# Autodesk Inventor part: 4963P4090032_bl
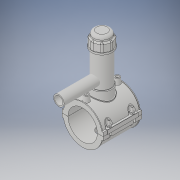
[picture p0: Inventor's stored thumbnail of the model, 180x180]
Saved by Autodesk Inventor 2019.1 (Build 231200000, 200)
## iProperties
Created: 2017-07
Part Number: 4963P4090032_bl
Material: Generic
Document SubType Name: Modeling
Designer: KIM
Density: 1 g/cm^3
Appearance: Default
Author: KIM
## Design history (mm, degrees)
derived "4963P4.ipt"
feature "Solid1::4963P4.ipt" dims "ScaleForDerivedMember" = 10
feature "Solid2::4963P4.ipt" dims "ScaleForDerivedMember" = 10
feature "Solid3::4963P4.ipt" dims "ScaleForDerivedMember" = 10
tag "TaggingFeature1"
body "Solid1"
body "Solid2"
body "Solid3"
other parameters: "d2" = 126 [user parameter], "d3" = 22.5 [user parameter], "d4" = 118 [user parameter], "d5" = 0 [user parameter], "d6" = 0.1 [user parameter], "d8" = 0 [user parameter], "d19" = 6 [user parameter], "d20" = 6 [user parameter], "d21" = 70.8 [user parameter], "d23" = 0 [user parameter], "d24" = 35.4 [user parameter], "d26" = 0 [user parameter], "d27" = 3 [user parameter], "d28" = 3 [user parameter], "d29" = 3 [user parameter], "d31" = 6 [user parameter], "d32" = 0 [user parameter], "d33" = 0 [user parameter], "d34" = 0.6 [user parameter], "d40" = 60.84 [user parameter], "d41" = 63 [user parameter], "d43" = 0 [user parameter], "d45" = 0 [user parameter], "d47" = 129.3 [user parameter], "d70" = 15 [user parameter], "d72" = 0 [user parameter], "d73" = 6 [user parameter], "d75" = 5 [user parameter], "d76" = 0 [user parameter], "d77" = 4.5 [user parameter], "d78" = 75 [user parameter], "d79" = 15 [user parameter], "d80" = 47.2 [user parameter], "d82" = 5 deg [user parameter], "d84" = 4 [user parameter], "d85" = 14 [user parameter], "d86" = 0 [user parameter], "d87" = 3 [user parameter], "d88" = 0 [user parameter], "d89" = 1 [user parameter], "d90" = 1 [user parameter], "d91" = 94.4 [user parameter], "d92" = 0 [user parameter], "d93" = 0.5 [user parameter], "d94" = 47.36842 [user parameter], "d96" = 119.34 [user parameter], "d97" = 2.36 [user parameter], "d98" = 0 [user parameter], "d102" = 0.9 [user parameter], "d120" = 140 deg [user parameter], "d121" = 24.228 [user parameter], "d122" = 20 deg [user parameter], "d123" = 234 [user parameter], "d124" = 70.2 [user parameter], "d126" = 0 [user parameter], "d143" = 92.7 [user parameter], "d145" = 20.76923 [user parameter], "d149" = 1.35 [user parameter], "d150" = 22.84615 [user parameter], "d153" = 118 [user parameter], "d154" = 0 [user parameter], "d156" = 58.5 [user parameter], "d157" = 160 deg [user parameter], "d159" = 5.4 [user parameter], "d161" = 1.35 [user parameter], "d162" = 70.8 [user parameter], "d163" = 0 [user parameter], "d164" = 45 [user parameter], "d167" = 9 [user parameter], "d168" = 57.07317 [user parameter], "d170" = 3.75 [user parameter], "d172" = 0 [user parameter], "d173" = 1 [user parameter], "d175" = 45 [user parameter], "d176" = 20 deg [user parameter], "d177" = 6.3 [user parameter], "d178" = 27 [user parameter], "d180" = 0 [user parameter], "d183" = 10.8 [user parameter], "d184" = 5.04 [user parameter], "d185" = 38.35 [user parameter], "d186" = 38.35 [user parameter], "d187" = 58.5 [user parameter], "d188" = 8.1 [user parameter], "d189" = 6.3 [user parameter], "d190" = 0 [user parameter], "d191" = 87.75 [user parameter], "d193" = 8 [user parameter], "d194" = 4.13 [user parameter], "d195" = 90 deg [user parameter], "d197" = 0 [user parameter], "d199" = 0 [user parameter], "d200" = 13.5 [user parameter], "d202" = 0 [user parameter], "d203" = 177 [user parameter], "d204" = 59.85 [user parameter], "d205" = 44.1 [user parameter], "d206" = 53.55 [user parameter], "d207" = 132.75 [user parameter], "d208" = 138.06 [user parameter], "d209" = 164.61 [user parameter], "d210" = 54.18 [user parameter], "d211" = 63 [user parameter], "d212" = 50.4 [user parameter], "d213" = 36 [user parameter], "d216" = 0 [user parameter], "d217" = 9 [user parameter], "d218" = 9 [user parameter], "d219" = 1.8 [user parameter], "d224" = 0 [user parameter], "d225" = 56 [user parameter], "d226" = 32 [user parameter], "d227" = 25.6 [user parameter], "d228" = 132 [user parameter], "d230" = 5.4 [user parameter], "B_" = 126 [user parameter], "L_" = 118 [user parameter], "d_t" = 6 [user parameter], "H_2" = 177 [user parameter], "H_1" = 56 [user parameter]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
